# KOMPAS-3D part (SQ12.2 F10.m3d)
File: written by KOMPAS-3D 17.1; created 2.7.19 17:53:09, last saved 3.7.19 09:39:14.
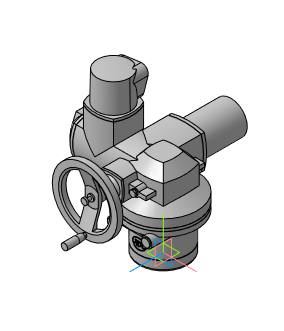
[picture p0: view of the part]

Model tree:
1. Операция без истории:2  (with: Сечение модели:1)

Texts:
  Точка начала. Х
  Точка начала. Y
  Точка начала. Z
